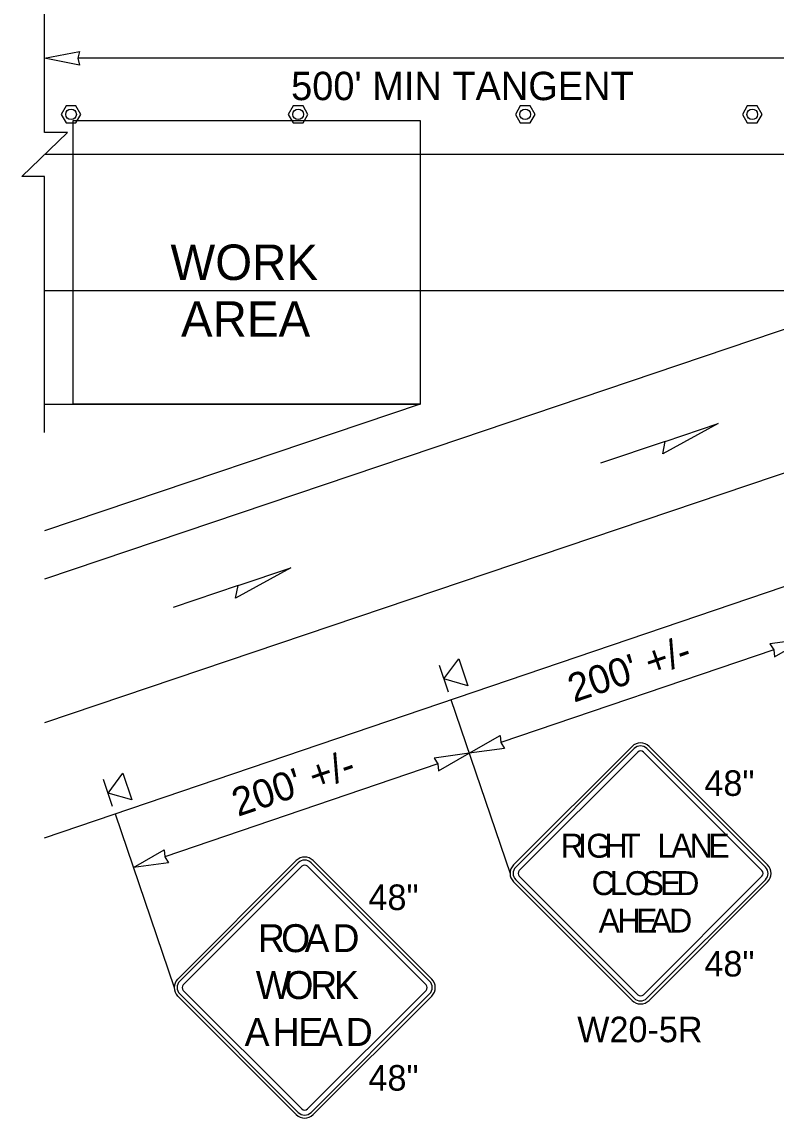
# Model space of a CAD drawing. Extents: x 99999 to 100116, y 99995 to 100013.
# Drawn here: x 100068.131 to 100070.257, y 100004.778 to 100007.868 of the extents above; entities that cross this region are included whole.
import ezdxf

# ---------------------------------------------------------------- set-up
doc = ezdxf.new("R2010")
doc.units = 0
for name, color, linetype in [('RD_MK_LineEdgeYellow', 7, 'Continuous'), ('RD_MK_LineLane', 7, 'Continuous'), ('TR_SN_ConstructionSigns', 7, 'Continuous'), ('TR_WZ_PortableSignMountBlk-Org', 7, 'Continuous'), ('TR_WZ_TallChanDevice', 7, 'Continuous'), ('TR_WZ_WorkAreaLabel', 7, 'Continuous'), ('TR_WZ_WorkZoneDetails', 7, 'Continuous'), ('TR_WZ_WorkZoneTextCurrent', 7, 'Continuous')]:
    doc.layers.add(name, color=color, linetype=linetype)

msp = doc.modelspace()

# ---------------------------------------------------------------- linework, layer by layer
at = {"layer": 'RD_MK_LineEdgeYellow'}
for p, q in [((100068.195, 100007.1109), (100069.2533, 100007.1109)), ((100070.6655, 100006.7269), (100068.195, 100005.8927)), ((100069.2943, 100006.6692), (100068.195, 100006.298))]:
    msp.add_line(p, q, dxfattribs=at)
at = {"layer": 'RD_MK_LineLane'}
msp.add_lwpolyline([(100075.43, 100007.4949), (100068.195, 100007.4949)], dxfattribs=at)
at = {"layer": 'TR_SN_ConstructionSigns'}
for p, q in [((100069.8509, 100005.8261), (100069.5168, 100005.492)), ((100069.8568, 100005.8202), (100069.5227, 100005.4861)), ((100069.5327, 100005.4761), (100069.8668, 100005.8102)), ((100069.8827, 100005.8102), (100070.2168, 100005.4761)), ((100070.2267, 100005.4861), (100069.8926, 100005.8202)), ((100070.2327, 100005.492), (100069.8986, 100005.8261)), ((100068.9041, 100005.5043), (100068.57, 100005.1702)), ((100068.91, 100005.4983), (100068.5759, 100005.1642)), ((100068.5859, 100005.1543), (100068.92, 100005.4884)), ((100068.9359, 100005.4884), (100069.27, 100005.1543)), ((100069.28, 100005.1642), (100068.9458, 100005.4983)), ((100069.2859, 100005.1702), (100068.9518, 100005.5043)), ((100069.8668, 100005.1261), (100069.5327, 100005.4602)), ((100070.2168, 100005.4602), (100069.8827, 100005.1261)), ((100069.5168, 100005.4443), (100069.8509, 100005.1102)), ((100069.5227, 100005.4503), (100069.8568, 100005.1162)), ((100069.8926, 100005.1162), (100070.2267, 100005.4503)), ((100069.8986, 100005.1102), (100070.2327, 100005.4443)), ((100068.57, 100005.1224), (100068.9041, 100004.7883)), ((100068.5759, 100005.1284), (100068.91, 100004.7943)), ((100068.92, 100004.8043), (100068.5859, 100005.1384)), ((100069.27, 100005.1384), (100068.9359, 100004.8043)), ((100068.9458, 100004.7943), (100069.28, 100005.1284)), ((100068.9518, 100004.7883), (100069.2859, 100005.1224))]:
    msp.add_line(p, q, dxfattribs=at)
for centre, radius, start, end in [((100069.8747, 100005.8023), 0.0338, 45, 135), ((100069.8747, 100005.8023), 0.0253, 45, 135), ((100069.8747, 100005.8023), 0.0113, 45, 135), ((100068.9279, 100005.4804), 0.0338, 45, 135), ((100068.9279, 100005.4804), 0.0253, 45, 135), ((100068.9279, 100005.4804), 0.0113, 45, 135), ((100069.5406, 100005.4682), 0.0338, 135, 225), ((100070.2088, 100005.4682), 0.0338, 315, 45), ((100069.5406, 100005.4682), 0.0253, 135, 225), ((100069.5406, 100005.4682), 0.0113, 135, 225), ((100070.2088, 100005.4682), 0.0113, 315, 45), ((100070.2088, 100005.4682), 0.0253, 315, 45), ((100068.5938, 100005.1463), 0.0338, 135, 225), ((100068.5938, 100005.1463), 0.0253, 135, 225), ((100068.5938, 100005.1463), 0.0113, 135, 225), ((100069.2621, 100005.1463), 0.0113, 315, 45), ((100069.2621, 100005.1463), 0.0253, 315, 45), ((100069.2621, 100005.1463), 0.0338, 315, 45), ((100069.8747, 100005.1341), 0.0113, 225, 315), ((100069.8747, 100005.1341), 0.0338, 225, 315), ((100069.8747, 100005.1341), 0.0253, 225, 315), ((100068.9279, 100004.8122), 0.0338, 225, 315), ((100068.9279, 100004.8122), 0.0253, 225, 315), ((100068.9279, 100004.8122), 0.0113, 225, 315)]:
    msp.add_arc(centre, radius, start, end, dxfattribs=at)
at = {"layer": 'TR_WZ_PortableSignMountBlk-Org'}
for p, q in [((100069.3333, 100005.9787), (100069.3076, 100006.0545)), ((100068.3865, 100005.6569), (100068.3608, 100005.7326))]:
    msp.add_line(p, q, dxfattribs=at)
for points in [[(100069.3205, 100006.0165), (100069.362, 100006.0729), (100069.3877, 100005.9972)], [(100068.3737, 100005.6947), (100068.4152, 100005.7511), (100068.4409, 100005.6753)]]:
    msp.add_lwpolyline(points, close=True, dxfattribs=at)
at = {"layer": 'TR_WZ_TallChanDevice'}
for points in [[(100068.2833, 100007.6319), (100068.2555, 100007.6319), (100068.2417, 100007.6079), (100068.2555, 100007.5839), (100068.2833, 100007.5839), (100068.2971, 100007.6079)], [(100068.9233, 100007.6319), (100068.8955, 100007.6319), (100068.8817, 100007.6079), (100068.8955, 100007.5839), (100068.9233, 100007.5839), (100068.9371, 100007.6079)], [(100069.5633, 100007.6319), (100069.5355, 100007.6319), (100069.5217, 100007.6079), (100069.5355, 100007.5839), (100069.5633, 100007.5839), (100069.5771, 100007.6079)], [(100070.2033, 100007.6319), (100070.1755, 100007.6319), (100070.1617, 100007.6079), (100070.1755, 100007.5839), (100070.2033, 100007.5839), (100070.2171, 100007.6079)]]:
    msp.add_lwpolyline(points, close=True, dxfattribs=at)
for points in [[(100068.2833, 100007.6319), (100068.2555, 100007.6319), (100068.2417, 100007.6079), (100068.2555, 100007.5839), (100068.2833, 100007.5839), (100068.2971, 100007.6079), (100068.2833, 100007.6319)], [(100068.9233, 100007.6319), (100068.8955, 100007.6319), (100068.8817, 100007.6079), (100068.8955, 100007.5839), (100068.9233, 100007.5839), (100068.9371, 100007.6079), (100068.9233, 100007.6319)], [(100069.5633, 100007.6319), (100069.5355, 100007.6319), (100069.5217, 100007.6079), (100069.5355, 100007.5839), (100069.5633, 100007.5839), (100069.5771, 100007.6079), (100069.5633, 100007.6319)], [(100070.2033, 100007.6319), (100070.1755, 100007.6319), (100070.1617, 100007.6079), (100070.1755, 100007.5839), (100070.2033, 100007.5839), (100070.2171, 100007.6079), (100070.2033, 100007.6319)]]:
    msp.add_lwpolyline(points, dxfattribs=at)
for centre in [(100068.2694, 100007.6079), (100068.9094, 100007.6079), (100069.5494, 100007.6079), (100070.1894, 100007.6079)]:
    msp.add_circle(centre, 0.015, dxfattribs=at)
at = {"layer": 'TR_WZ_WorkZoneDetails'}
for p, q in [((100070.5087, 100007.7659), (100068.2887, 100007.7659)), ((100069.2533, 100007.1109), (100070.6024, 100007.1109)), ((100070.6024, 100007.1109), (100069.2943, 100006.6692)), ((100068.195, 100006.7909), (100069.2533, 100006.7909)), ((100069.2533, 100006.7909), (100068.195, 100006.4338)), ((100069.9441, 100006.6859), (100069.7613, 100006.6242)), ((100068.195, 100005.5689), (100070.6601, 100006.4069)), ((100068.7404, 100006.2795), (100068.5576, 100006.2178)), ((100070.2498, 100006.0985), (100069.4805, 100005.8369)), ((100069.3403, 100005.9583), (100069.5069, 100005.4682)), ((100069.303, 100005.7766), (100068.5337, 100005.5151)), ((100068.3935, 100005.6364), (100068.5601, 100005.1463))]:
    msp.add_line(p, q, dxfattribs=at)
msp.add_lwpolyline([(100068.195, 100006.7109), (100068.195, 100007.433), (100068.131, 100007.433), (100068.259, 100007.5569), (100068.195, 100007.5569), (100068.195, 100008.0869)], dxfattribs=at)
for points in [[(100068.195, 100007.7659), (100068.2933, 100007.7851), (100068.2887, 100007.7659), (100068.2933, 100007.7466)], [(100068.275, 100006.7909), (100068.275, 100007.5909), (100069.2533, 100007.5909), (100069.2533, 100006.7909)], [(100070.093, 100006.7362), (100069.9371, 100006.651), (100069.9441, 100006.6859)], [(100068.8893, 100006.3298), (100068.7333, 100006.2445), (100068.7404, 100006.2795)], [(100070.3386, 100006.1286), (100070.2393, 100006.1152), (100070.2498, 100006.0985), (100070.2517, 100006.0787)], [(100069.3918, 100005.8068), (100069.4786, 100005.8567), (100069.4805, 100005.8369), (100069.491, 100005.8202)], [(100069.3918, 100005.8068), (100069.2925, 100005.7934), (100069.303, 100005.7766), (100069.3049, 100005.7569)], [(100068.445, 100005.4849), (100068.5318, 100005.5348), (100068.5337, 100005.5151), (100068.5442, 100005.4983)]]:
    msp.add_lwpolyline(points, close=True, dxfattribs=at)

# ---------------------------------------------------------------- texts
at = {"layer": 'TR_SN_ConstructionSigns'}
for s, height, p in [('48"', 0.072, (100070.0545, 100005.6867)), ('G', 0.0675, (100069.7215, 100005.5125)), ('R', 0.0675, (100069.6493, 100005.5125)), ('I', 0.0675, (100069.6986, 100005.5125)), ('H', 0.0675, (100069.7728, 100005.5125)), ('T', 0.0675, (100069.8201, 100005.5125)), ('L', 0.0675, (100069.922, 100005.5125)), ('A', 0.0675, (100069.9605, 100005.5125)), ('N', 0.0675, (100070.0131, 100005.5125)), ('E', 0.0675, (100070.0658, 100005.5125)), ('C', 0.0675, (100069.7364, 100005.407)), ('L', 0.0675, (100069.7877, 100005.407)), ('O', 0.0675, (100069.8302, 100005.407)), ('S', 0.0675, (100069.8801, 100005.407)), ('E', 0.0675, (100069.9294, 100005.407)), ('D', 0.0675, (100069.9753, 100005.407)), ('48"', 0.072, (100069.1077, 100005.3649)), ('A', 0.0675, (100069.7566, 100005.3015)), ('H', 0.0675, (100069.8093, 100005.3015)), ('E', 0.0675, (100069.8619, 100005.3015)), ('A', 0.0675, (100069.9024, 100005.3015)), ('D', 0.0675, (100069.9551, 100005.3015)), ('R', 0.0788, (100068.796, 100005.2462)), ('O', 0.0788, (100068.8614, 100005.2462)), ('A', 0.0788, (100068.9276, 100005.2462)), ('D', 0.0788, (100069.0063, 100005.2462)), ('48"', 0.072, (100070.0545, 100005.1776)), ('W', 0.0788, (100068.7901, 100005.114)), ('O', 0.0788, (100068.8705, 100005.114)), ('R', 0.0788, (100068.9437, 100005.114)), ('K', 0.0788, (100069.0106, 100005.114)), ('A', 0.0788, (100068.7586, 100004.9818)), ('H', 0.0788, (100068.8374, 100004.9818)), ('E', 0.0788, (100068.9098, 100004.9818)), ('A', 0.0788, (100068.965, 100004.9818)), ('D', 0.0788, (100069.0437, 100004.9818)), ('W20-5R', 0.072, (100069.6961, 100004.9923)), ('48"', 0.072, (100069.1077, 100004.8558))]:
    msp.add_text(s, height=height, rotation=360, dxfattribs=at).set_placement(p)
at = {"layer": 'TR_WZ_WorkAreaLabel'}
for s, p in [('WORK', (100068.5496, 100007.1409)), ('AREA', (100068.5793, 100006.9809))]:
    msp.add_text(s, height=0.1, dxfattribs=at).set_placement(p)
at = {"layer": 'TR_WZ_WorkZoneTextCurrent'}
msp.add_text("500' MIN TANGENT", height=0.08, dxfattribs=at).set_placement((100068.8897, 100007.6479))
for p in [(100069.6866, 100005.9492), (100068.7398, 100005.6274)]:
    msp.add_text("200' +/-", height=0.08, rotation=18.775, dxfattribs=at).set_placement(p)

doc.saveas('drawing.dxf')
